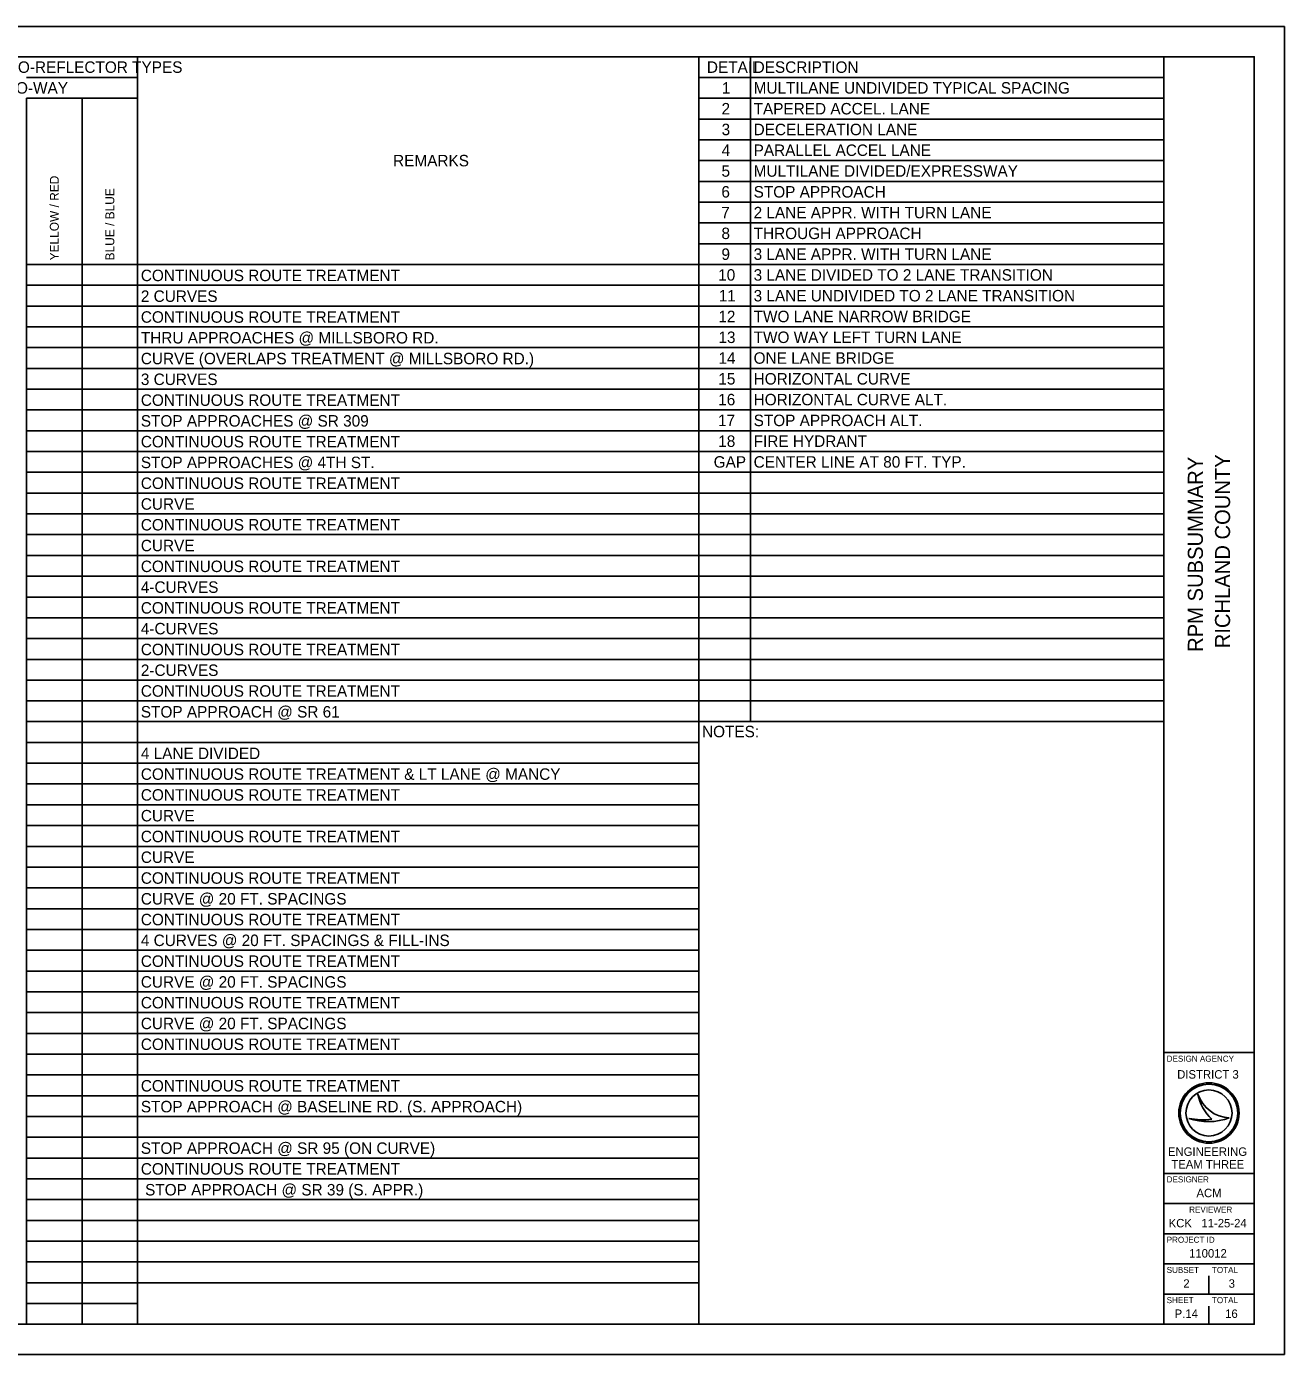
# Model space of a CAD drawing. Extents: x 0 to 34, y 0 to 22.
# Drawn here: x 13.17 to 34, y 0 to 22 of the extents above; entities that cross this region are included whole.
import ezdxf

# ---------------------------------------------------------------- set-up
doc = ezdxf.new("R2010")
doc.units = 0
for name, color, linetype in [('SH_Border', 7, 'Continuous'), ('SH_Cut_Line', 7, 'Continuous'), ('SH_Data', 7, 'Continuous'), ('SH_Text', 7, 'Continuous')]:
    doc.layers.add(name, color=color, linetype=linetype)

msp = doc.modelspace()

# ---------------------------------------------------------------- linework, layer by layer
at = {"layer": 'SH_Border'}
for p, q in [((32, 0.5), (32, 21.5)), ((32, 5), (33.5, 5)), ((32, 3), (33.5, 3)), ((32, 2.5), (33.5, 2.5)), ((32, 2), (33.5, 2)), ((32, 1.5), (33.5, 1.5)), ((32, 1), (33.5, 1))]:
    msp.add_line(p, q, dxfattribs=at)
msp.add_lwpolyline([(1.5, 21.5), (33.5, 21.5), (33.5, 0.5), (1.5, 0.5)], close=True, dxfattribs=at)
at = {"layer": 'SH_Cut_Line'}
msp.add_lwpolyline([(0, 0), (34, 0), (34, 22), (0, 22)], close=True, dxfattribs=at)
at = {"layer": 'SH_Data'}
for p, q in [((32.567, 4.31), (32.567, 4.31)), ((32.75, 4), (32.75, 4)), ((32.417, 3.91), (32.417, 3.91)), ((33.087, 3.919), (33.087, 3.919)), ((32.75, 1), (32.75, 1.3)), ((32.375, 0.675), (32.375, 0.675)), ((32.75, 0.5), (32.75, 0.8))]:
    msp.add_line(p, q, dxfattribs=at)
for radius in [0.5, 0.477, 0.477, 0.382]:
    msp.add_circle((32.75, 4), radius, dxfattribs=at)
for centre, radius, start, end in [((33.116, 4.498), 0.58, 198.9257, 198.9319), ((33.347, 4.47), 0.796, 191.6379, 191.6421), ((33.116, 4.498), 0.58, 198.9319, 267.1657), ((33.347, 4.47), 0.796, 191.6421, 226.0947), ((32.739, 4.87), 1.013, 251.4576, 290.0832), ((32.648, 5.154), 1.266, 259.4964, 259.4995), ((32.739, 4.87), 1.013, 251.4527, 251.4576), ((32.648, 5.154), 1.266, 259.4995, 276.6672)]:
    msp.add_arc(centre, radius, start, end, dxfattribs=at)
at = {"layer": 'SH_Text'}
for p, q in [((13.167, 21.5), (32, 21.5)), ((15.007, 21.5), (15.007, 0.5)), ((24.3, 21.5), (24.3, 0.5)), ((25.156, 21.5), (25.156, 10.484)), ((32, 21.5), (32, 0.5)), ((13.167, 21.156), (15.007, 21.156)), ((24.3, 21.156), (32, 21.156)), ((13.167, 20.811), (15.007, 20.811)), ((13.167, 20.811), (13.167, 0.5)), ((14.087, 20.811), (14.087, 0.5)), ((24.3, 20.811), (32, 20.811)), ((24.3, 20.467), (32, 20.467)), ((24.3, 20.123), (32, 20.123)), ((24.3, 19.779), (32, 19.779)), ((24.3, 19.434), (32, 19.434)), ((24.3, 19.09), (32, 19.09)), ((24.3, 18.746), (32, 18.746)), ((24.3, 18.402), (32, 18.402)), ((13.167, 18.057), (32, 18.057)), ((13.167, 17.713), (32, 17.713)), ((13.167, 17.369), (32, 17.369)), ((13.167, 17.025), (32, 17.025)), ((13.167, 16.68), (32, 16.68)), ((13.167, 16.336), (32, 16.336)), ((13.167, 15.992), (32, 15.992)), ((13.167, 15.648), (32, 15.648)), ((13.167, 15.303), (32, 15.303)), ((13.167, 14.959), (32, 14.959)), ((13.167, 14.615), (32, 14.615)), ((13.167, 14.27), (32, 14.27)), ((13.167, 13.926), (32, 13.926)), ((13.167, 13.582), (32, 13.582)), ((13.167, 13.238), (32, 13.238)), ((13.167, 12.893), (32, 12.893)), ((13.167, 12.549), (32, 12.549)), ((13.167, 12.205), (32, 12.205)), ((13.167, 11.861), (32, 11.861)), ((13.167, 11.516), (32, 11.516)), ((13.167, 11.172), (32, 11.172)), ((13.167, 10.828), (32, 10.828)), ((13.167, 10.484), (32, 10.484)), ((13.167, 10.139), (24.3, 10.139)), ((13.167, 9.795), (24.3, 9.795)), ((13.167, 9.451), (24.3, 9.451)), ((13.167, 9.107), (24.3, 9.107)), ((13.167, 8.762), (24.3, 8.762)), ((13.167, 8.418), (24.3, 8.418)), ((13.167, 8.074), (24.3, 8.074)), ((13.167, 7.73), (24.3, 7.73)), ((13.167, 7.385), (24.3, 7.385)), ((13.167, 7.041), (24.3, 7.041)), ((13.167, 6.697), (24.3, 6.697)), ((13.167, 6.352), (24.3, 6.352)), ((13.167, 6.008), (24.3, 6.008)), ((13.167, 5.664), (24.3, 5.664)), ((13.167, 5.32), (24.3, 5.32)), ((13.167, 4.975), (24.3, 4.975)), ((13.167, 4.631), (24.3, 4.631)), ((13.167, 4.287), (24.3, 4.287)), ((13.167, 3.943), (24.3, 3.943)), ((13.167, 3.598), (24.3, 3.598)), ((13.167, 3.254), (24.3, 3.254)), ((13.167, 2.91), (24.3, 2.91)), ((13.167, 2.566), (24.3, 2.566)), ((13.167, 2.221), (24.3, 2.221)), ((13.167, 1.877), (24.3, 1.877)), ((13.167, 1.533), (24.3, 1.533)), ((13.167, 1.189), (15.007, 1.189)), ((15.007, 1.189), (24.3, 1.189)), ((13.167, 0.844), (15.007, 0.844)), ((13.167, 0.5), (24.3, 0.5)), ((24.3, 0.5), (32, 0.5))]:
    msp.add_line(p, q, dxfattribs=at)

# ---------------------------------------------------------------- texts
at = {"layer": 'SH_Data'}
for s, p in [('RPM SUBSUMMARY', (32.65, 11.64)), ('RICHLAND COUNTY', (33.1, 11.7))]:
    msp.add_text(s, height=0.25, rotation=90, dxfattribs=at).set_placement(p)
for s, height, p in [('DESIGN AGENCY', 0.1, (32.05, 4.85)), ('DISTRICT 3', 0.14, (32.224, 4.57)), ('ENGINEERING', 0.14, (32.071, 3.29)), ('TEAM THREE', 0.14, (32.127, 3.08)), ('DESIGNER', 0.1, (32.05, 2.85)), ('ACM', 0.14, (32.543, 2.605)), ('REVIEWER', 0.1, (32.422, 2.35)), ('KCK', 0.14, (32.083, 2.105)), ('11-25-24', 0.14, (32.625, 2.105)), ('PROJECT ID', 0.1, (32.05, 1.85)), ('110012', 0.14, (32.421, 1.605)), ('SUBSET', 0.1, (32.05, 1.35)), ('TOTAL', 0.1, (32.8, 1.35)), ('2', 0.14, (32.325, 1.105)), ('3', 0.14, (33.076, 1.105)), ('SHEET', 0.1, (32.05, 0.85)), ('TOTAL', 0.1, (32.8, 0.85)), ('P.14', 0.14, (32.182, 0.605)), ('16', 0.14, (33.018, 0.605))]:
    msp.add_text(s, height=height, dxfattribs=at).set_placement(p)
at = {"layer": 'SH_Text'}
for s, height, p in [('PRISMATIC RETRO-REFLECTOR TYPES', 0.19003, (10.878, 21.233)), ('DETAIL', 0.19, (24.435, 21.233)), ('DESCRIPTION', 0.19003, (25.209, 21.233)), ('TWO-WAY', 0.19, (12.598, 20.889)), ('1', 0.19, (24.684, 20.889)), ('MULTILANE UNDIVIDED TYPICAL SPACING', 0.19003, (25.209, 20.889)), ('2', 0.19, (24.678, 20.544)), ('TAPERED ACCEL. LANE', 0.19003, (25.209, 20.544)), ('3', 0.19, (24.679, 20.2)), ('DECELERATION LANE', 0.19003, (25.209, 20.2)), ('4', 0.19, (24.679, 19.856)), ('PARALLEL ACCEL LANE', 0.19003, (25.209, 19.856)), ('REMARKS', 0.19, (19.238, 19.684)), ('5', 0.19, (24.677, 19.512)), ('MULTILANE DIVIDED/EXPRESSWAY', 0.19003, (25.209, 19.512)), ('6', 0.19, (24.675, 19.167)), ('STOP APPROACH', 0.19003, (25.209, 19.167)), ('7', 0.19, (24.672, 18.823)), ('2 LANE APPR. WITH TURN LANE', 0.19003, (25.209, 18.823)), ('8', 0.19, (24.676, 18.479)), ('THROUGH APPROACH', 0.19003, (25.209, 18.479)), ('9', 0.19, (24.676, 18.134)), ('3 LANE APPR. WITH TURN LANE', 0.19003, (25.209, 18.134)), ('CONTINUOUS ROUTE TREATMENT', 0.19003, (15.06, 17.782)), ('10', 0.19, (24.622, 17.79)), ('3 LANE DIVIDED TO 2 LANE TRANSITION', 0.19003, (25.209, 17.79)), ('2 CURVES', 0.19, (15.06, 17.438)), ('11', 0.19, (24.631, 17.446)), ('3 LANE UNDIVIDED TO 2 LANE TRANSITION', 0.19003, (25.209, 17.446)), ('CONTINUOUS ROUTE TREATMENT', 0.19003, (15.06, 17.093)), ('12', 0.19, (24.625, 17.102)), ('TWO LANE NARROW BRIDGE', 0.19003, (25.209, 17.102)), ('THRU APPROACHES @ MILLSBORO RD.', 0.19003, (15.06, 16.749)), ('13', 0.19, (24.626, 16.757)), ('TWO WAY LEFT TURN LANE', 0.19003, (25.209, 16.757)), ('CURVE (OVERLAPS TREATMENT @ MILLSBORO RD.)', 0.19003, (15.06, 16.405)), ('14', 0.19, (24.626, 16.413)), ('ONE LANE BRIDGE', 0.19003, (25.209, 16.413)), ('3 CURVES', 0.19, (15.06, 16.061)), ('15', 0.19, (24.624, 16.069)), ('HORIZONTAL CURVE', 0.19003, (25.209, 16.069)), ('CONTINUOUS ROUTE TREATMENT', 0.19003, (15.06, 15.716)), ('16', 0.19, (24.622, 15.725)), ('HORIZONTAL CURVE ALT.', 0.19003, (25.209, 15.725)), ('STOP APPROACHES @ SR 309', 0.19003, (15.06, 15.372)), ('17', 0.19, (24.619, 15.38)), ('STOP APPROACH ALT.', 0.19003, (25.209, 15.38)), ('CONTINUOUS ROUTE TREATMENT', 0.19003, (15.06, 15.028)), ('18', 0.19, (24.623, 15.036)), ('FIRE HYDRANT', 0.19003, (25.209, 15.036)), ('STOP APPROACHES @ 4TH ST.', 0.19003, (15.06, 14.684)), ('GAP', 0.19, (24.547, 14.692)), ('CENTER LINE AT 80 FT. TYP.', 0.19003, (25.209, 14.692)), ('CONTINUOUS ROUTE TREATMENT', 0.19003, (15.06, 14.339)), ('CURVE', 0.19, (15.06, 13.995)), ('CONTINUOUS ROUTE TREATMENT', 0.19003, (15.06, 13.651)), ('CURVE', 0.19, (15.06, 13.307)), ('CONTINUOUS ROUTE TREATMENT', 0.19003, (15.06, 12.962)), ('4-CURVES', 0.19, (15.06, 12.618)), ('CONTINUOUS ROUTE TREATMENT', 0.19003, (15.06, 12.274)), ('4-CURVES', 0.19, (15.06, 11.93)), ('CONTINUOUS ROUTE TREATMENT', 0.19003, (15.06, 11.585)), ('2-CURVES', 0.19, (15.06, 11.241)), ('CONTINUOUS ROUTE TREATMENT', 0.19003, (15.06, 10.897)), ('STOP APPROACH @ SR 61', 0.19003, (15.06, 10.552)), ('NOTES:', 0.19, (24.354, 10.225)), ('4 LANE DIVIDED', 0.19003, (15.06, 9.864)), ('CONTINUOUS ROUTE TREATMENT & LT LANE @ MANCY', 0.19003, (15.06, 9.52)), ('CONTINUOUS ROUTE TREATMENT', 0.19003, (15.06, 9.175)), ('CURVE', 0.19, (15.06, 8.831)), ('CONTINUOUS ROUTE TREATMENT', 0.19003, (15.06, 8.487)), ('CURVE', 0.19, (15.06, 8.143)), ('CONTINUOUS ROUTE TREATMENT', 0.19003, (15.06, 7.798)), ('CURVE @ 20 FT. SPACINGS', 0.19003, (15.06, 7.454)), ('CONTINUOUS ROUTE TREATMENT', 0.19003, (15.06, 7.11)), ('4 CURVES @ 20 FT. SPACINGS & FILL-INS', 0.19003, (15.06, 6.766)), ('CONTINUOUS ROUTE TREATMENT', 0.19003, (15.06, 6.421)), ('CURVE @ 20 FT. SPACINGS', 0.19003, (15.06, 6.077)), ('CONTINUOUS ROUTE TREATMENT', 0.19003, (15.06, 5.733)), ('CURVE @ 20 FT. SPACINGS', 0.19003, (15.06, 5.389)), ('CONTINUOUS ROUTE TREATMENT', 0.19003, (15.06, 5.044)), ('CONTINUOUS ROUTE TREATMENT', 0.19003, (15.06, 4.356)), ('STOP APPROACH @ BASELINE RD. (S. APPROACH)', 0.19003, (15.06, 4.011)), ('STOP APPROACH @ SR 95 (ON CURVE)', 0.19003, (15.06, 3.323)), ('CONTINUOUS ROUTE TREATMENT', 0.19003, (15.06, 2.979)), (' STOP APPROACH @ SR 39 (S. APPR.)', 0.19003, (15.06, 2.634))]:
    msp.add_text(s, height=height, dxfattribs=at).set_placement(p)
for s, p in [('YELLOW / RED', (13.701, 18.126)), ('BLUE / BLUE', (14.621, 18.126))]:
    msp.add_text(s, height=0.14758, rotation=90, dxfattribs=at).set_placement(p)

doc.saveas('drawing.dxf')
